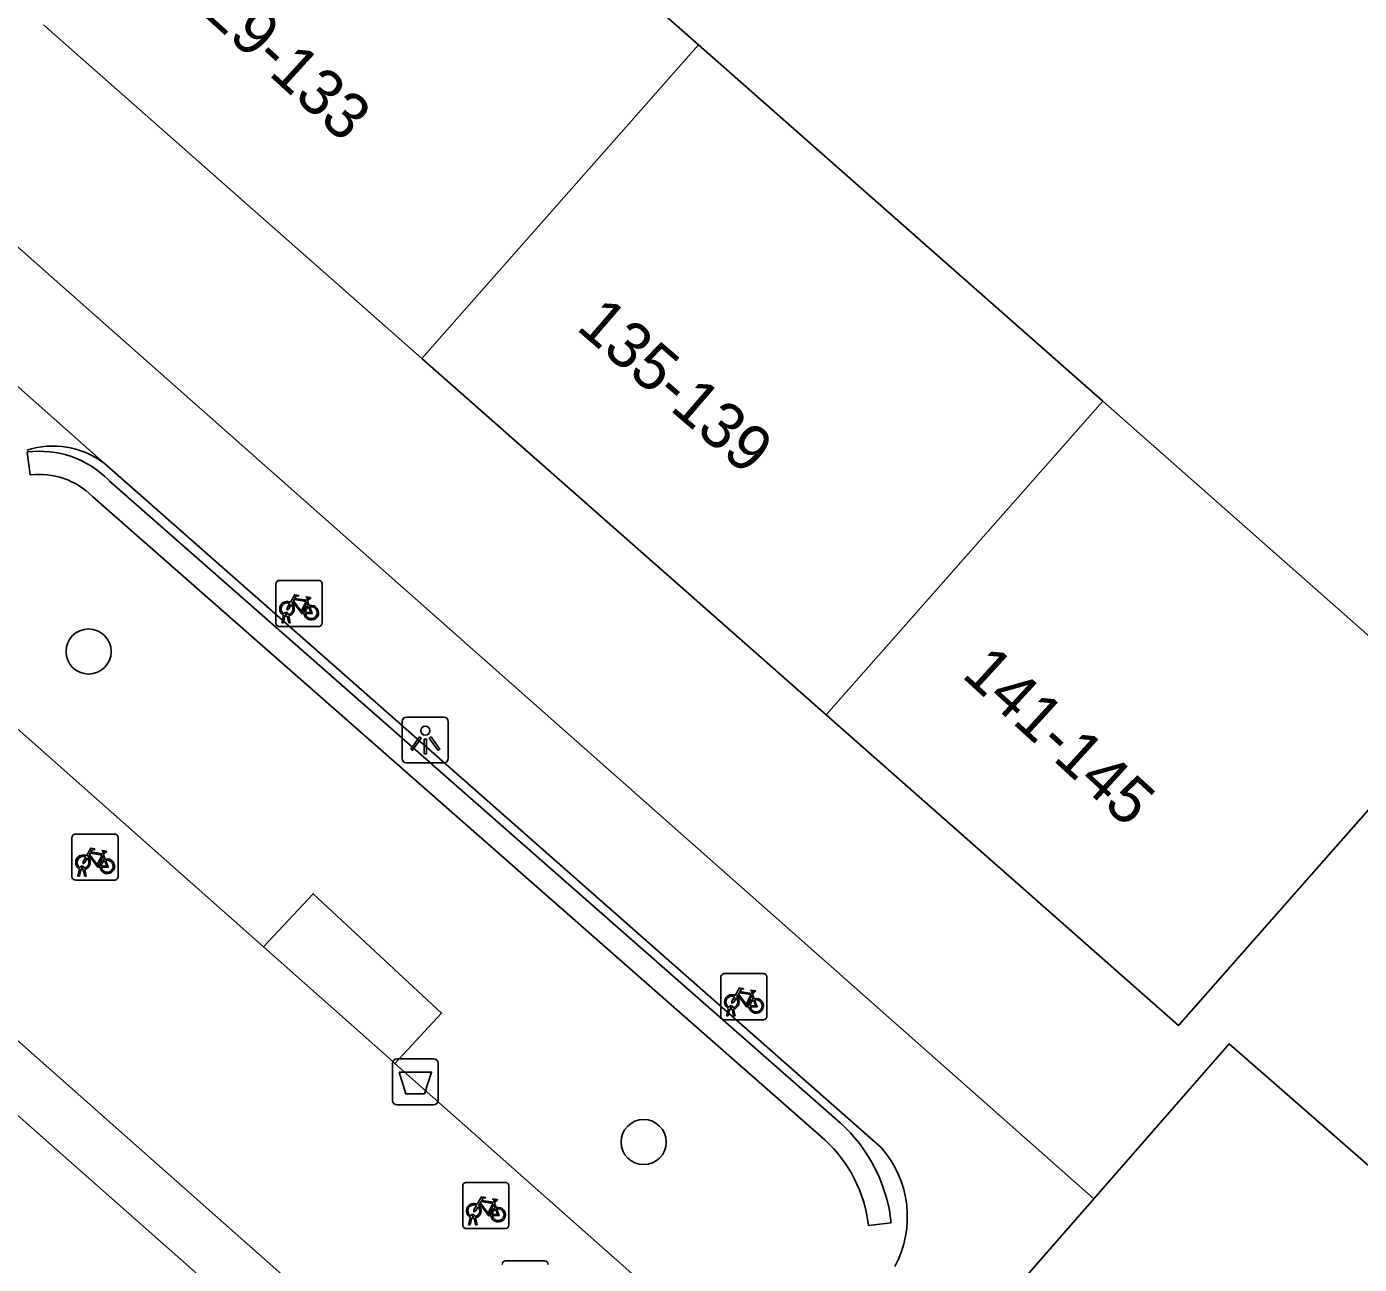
# Model space of a CAD drawing. Extents: x 162074 to 163034, y 381824 to 382557.
# Drawn here: x 162669.05 to 162697.93, y 382160.42 to 382187.25 of the extents above; entities that cross this region are included whole.
import ezdxf

# ---------------------------------------------------------------- set-up
doc = ezdxf.new("R2010")
doc.units = 0
for name, color, linetype in [('IMGEO_Afvalbak', 7, 'Continuous'), ('IMGEO_Boom', 7, 'Continuous'), ('IMGEO_Brandkraan', 7, 'Continuous'), ('IMGEO_Fietsenrek', 7, 'Continuous'), ('IMGEO_Fietspad_gesloten', 7, 'Continuous'), ('IMGEO_Haag', 7, 'Continuous'), ('IMGEO_Lichtpunt', 7, 'Continuous'), ('IMGEO_Pand', 7, 'Continuous'), ('IMGEO_Pand_nummerreeks', 7, 'Continuous'), ('IMGEO_Rijbaan_lokaal_open', 7, 'Continuous'), ('IMGEO_Voetpad_gesloten', 7, 'Continuous'), ('IMGEO_Voetpad_open', 7, 'Continuous')]:
    doc.layers.add(name, color=color, linetype=linetype)

msp = doc.modelspace()

# ---------------------------------------------------------------- linework, layer by layer
at = {"layer": 'IMGEO_Afvalbak'}
for p, q in [((162676.974, 382163.977), (162676.974, 382164.777)), ((162676.974, 382164.777), (162676.974, 382163.977)), ((162677.074, 382164.877), (162677.864, 382164.877)), ((162677.864, 382164.877), (162677.074, 382164.877)), ((162677.964, 382164.777), (162677.964, 382163.977)), ((162677.964, 382163.977), (162677.964, 382164.777)), ((162677.864, 382163.877), (162677.074, 382163.877)), ((162677.074, 382163.877), (162677.864, 382163.877))]:
    msp.add_line(p, q, dxfattribs=at)
msp.add_lwpolyline([(162677.117, 382164.591), (162677.821, 382164.591), (162677.672, 382164.121), (162677.266, 382164.121), (162677.117, 382164.591)], dxfattribs=at)
for centre, start, end in [((162677.074, 382164.777), 90, 180), ((162677.074, 382164.777), 90, 180), ((162677.864, 382164.777), 0, 90), ((162677.864, 382164.777), 360, 90), ((162677.074, 382163.977), 180, 270), ((162677.074, 382163.977), 180, 270), ((162677.864, 382163.977), 270, 0), ((162677.864, 382163.977), 270, 0)]:
    msp.add_arc(centre, 0.1, start, end, dxfattribs=at)
at = {"layer": 'IMGEO_Boom'}
for centre in [(162670.389, 382173.706), (162682.419, 382163.073)]:
    msp.add_circle(centre, 0.489, dxfattribs=at)
at = {"layer": 'IMGEO_Brandkraan'}
msp.add_line((162679.424, 382160.496), (162680.276, 382160.496), dxfattribs=at)
msp.add_lwpolyline([(162679.424, 382160.496), (162680.276, 382160.496)], dxfattribs=at)
for centre, start, end in [((162679.426, 382160.42), 91.552, 178.448), ((162679.426, 382160.42), 91.552, 178.448), ((162680.274, 382160.42), 1.552, 88.448), ((162680.274, 382160.42), 1.552, 88.448)]:
    msp.add_arc(centre, 0.0765, start, end, dxfattribs=at)
at = {"layer": 'IMGEO_Fietsenrek'}
for p, q in [((162674.449, 382174.322), (162674.449, 382175.163)), ((162674.449, 382175.163), (162674.449, 382174.322)), ((162674.524, 382175.247), (162675.365, 382175.247)), ((162675.365, 382175.247), (162674.524, 382175.247)), ((162675.449, 382175.172), (162675.449, 382174.331)), ((162675.449, 382174.331), (162675.449, 382175.172)), ((162675.136, 382174.796), (162675.172, 382174.701)), ((162674.576, 382174.331), (162674.615, 382174.491)), ((162674.645, 382174.479), (162674.61, 382174.331)), ((162674.687, 382174.503), (162674.686, 382174.507)), ((162674.728, 382174.331), (162674.694, 382174.473)), ((162674.718, 382174.514), (162674.719, 382174.507)), ((162674.726, 382174.477), (162674.761, 382174.331)), ((162675.374, 382174.247), (162674.533, 382174.247)), ((162674.533, 382174.247), (162675.374, 382174.247)), ((162674.61, 382174.331), (162674.576, 382174.331)), ((162674.761, 382174.331), (162674.728, 382174.331)), ((162670.028, 382168.825), (162670.028, 382169.666)), ((162670.028, 382169.666), (162670.028, 382168.825)), ((162670.103, 382169.75), (162670.944, 382169.75)), ((162670.944, 382169.75), (162670.103, 382169.75)), ((162671.028, 382169.675), (162671.028, 382168.834)), ((162671.028, 382168.834), (162671.028, 382169.675)), ((162670.715, 382169.299), (162670.751, 382169.204)), ((162670.155, 382168.834), (162670.194, 382168.994)), ((162670.224, 382168.982), (162670.189, 382168.834)), ((162670.266, 382169.006), (162670.265, 382169.01)), ((162670.307, 382168.834), (162670.273, 382168.976)), ((162670.297, 382169.017), (162670.298, 382169.01)), ((162670.305, 382168.98), (162670.34, 382168.834)), ((162670.953, 382168.75), (162670.112, 382168.75)), ((162670.112, 382168.75), (162670.953, 382168.75)), ((162670.189, 382168.834), (162670.155, 382168.834)), ((162670.34, 382168.834), (162670.307, 382168.834)), ((162684.09, 382165.799), (162684.09, 382166.64)), ((162684.09, 382166.64), (162684.09, 382165.799)), ((162684.165, 382166.724), (162685.006, 382166.724)), ((162685.006, 382166.724), (162684.165, 382166.724)), ((162685.09, 382166.649), (162685.09, 382165.808)), ((162685.09, 382165.808), (162685.09, 382166.649)), ((162684.777, 382166.273), (162684.813, 382166.178)), ((162684.217, 382165.808), (162684.256, 382165.968)), ((162684.251, 382165.808), (162684.217, 382165.808)), ((162684.286, 382165.956), (162684.251, 382165.808)), ((162684.328, 382165.98), (162684.327, 382165.984)), ((162684.369, 382165.808), (162684.335, 382165.95)), ((162684.359, 382165.991), (162684.36, 382165.984)), ((162684.367, 382165.954), (162684.402, 382165.808)), ((162684.402, 382165.808), (162684.369, 382165.808)), ((162685.015, 382165.724), (162684.174, 382165.724)), ((162684.174, 382165.724), (162685.015, 382165.724)), ((162678.497, 382161.273), (162678.497, 382162.114)), ((162678.497, 382162.114), (162678.497, 382161.273)), ((162678.572, 382162.198), (162679.413, 382162.198)), ((162679.413, 382162.198), (162678.572, 382162.198)), ((162679.497, 382162.123), (162679.497, 382161.282)), ((162679.497, 382161.282), (162679.497, 382162.123)), ((162679.184, 382161.747), (162679.22, 382161.652)), ((162678.624, 382161.282), (162678.663, 382161.442)), ((162678.693, 382161.43), (162678.658, 382161.282)), ((162678.735, 382161.454), (162678.734, 382161.458)), ((162678.766, 382161.465), (162678.767, 382161.458)), ((162678.774, 382161.428), (162678.809, 382161.282)), ((162679.422, 382161.198), (162678.581, 382161.198)), ((162678.581, 382161.198), (162679.422, 382161.198)), ((162678.658, 382161.282), (162678.624, 382161.282)), ((162678.776, 382161.282), (162678.742, 382161.424)), ((162678.809, 382161.282), (162678.776, 382161.282))]:
    msp.add_line(p, q, dxfattribs=at)
for points in [[(162674.783, 382174.721), (162674.731, 382174.631), (162674.691, 382174.606), (162674.692, 382174.653), (162674.747, 382174.747)], [(162674.762, 382174.773), (162674.857, 382174.937), (162674.943, 382174.923), (162674.945, 382174.914), (162674.889, 382174.903), (162674.862, 382174.858), (162675.118, 382174.817)], [(162675.058, 382174.529), (162675.008, 382174.529), (162674.817, 382174.78), (162674.798, 382174.748)], [(162675.105, 382174.792), (162674.848, 382174.833), (162674.831, 382174.804), (162674.998, 382174.584), (162675.105, 382174.792)], [(162675.153, 382174.694), (162675.123, 382174.771), (162675.014, 382174.553), (162675.057, 382174.553)], [(162675.118, 382174.817), (162675.143, 382174.866), (162675.137, 382174.87), (162675.114, 382174.874), (162675.102, 382174.881), (162675.101, 382174.884), (162675.103, 382174.889), (162675.198, 382174.874), (162675.2, 382174.864), (162675.19, 382174.851), (162675.178, 382174.845), (162675.164, 382174.851), (162675.136, 382174.796)], [(162675.087, 382174.553), (162675.207, 382174.552), (162675.163, 382174.666)], [(162675.183, 382174.673), (162675.238, 382174.528), (162675.088, 382174.528)], [(162670.362, 382169.224), (162670.31, 382169.134), (162670.27, 382169.109), (162670.271, 382169.156), (162670.326, 382169.25)], [(162670.341, 382169.276), (162670.436, 382169.44), (162670.522, 382169.426), (162670.524, 382169.417), (162670.468, 382169.406), (162670.441, 382169.361), (162670.697, 382169.32)], [(162670.637, 382169.032), (162670.587, 382169.032), (162670.396, 382169.283), (162670.377, 382169.251)], [(162670.684, 382169.295), (162670.427, 382169.336), (162670.41, 382169.307), (162670.577, 382169.087), (162670.684, 382169.295)], [(162670.732, 382169.197), (162670.702, 382169.274), (162670.593, 382169.056), (162670.636, 382169.056)], [(162670.697, 382169.32), (162670.722, 382169.369), (162670.716, 382169.373), (162670.693, 382169.377), (162670.681, 382169.384), (162670.68, 382169.387), (162670.682, 382169.392), (162670.777, 382169.377), (162670.779, 382169.367), (162670.769, 382169.354), (162670.757, 382169.348), (162670.743, 382169.354), (162670.715, 382169.299)], [(162670.666, 382169.056), (162670.786, 382169.055), (162670.742, 382169.169)], [(162670.762, 382169.176), (162670.817, 382169.031), (162670.667, 382169.031)], [(162684.403, 382166.25), (162684.498, 382166.414), (162684.584, 382166.4), (162684.586, 382166.391), (162684.53, 382166.38), (162684.503, 382166.335), (162684.759, 382166.294)], [(162684.759, 382166.294), (162684.784, 382166.343), (162684.778, 382166.347), (162684.755, 382166.351), (162684.743, 382166.358), (162684.742, 382166.361), (162684.744, 382166.366), (162684.839, 382166.351), (162684.841, 382166.341), (162684.831, 382166.328), (162684.819, 382166.322), (162684.805, 382166.328), (162684.777, 382166.273)], [(162684.424, 382166.198), (162684.372, 382166.108), (162684.332, 382166.083), (162684.333, 382166.13), (162684.388, 382166.224)], [(162684.699, 382166.006), (162684.649, 382166.006), (162684.458, 382166.257), (162684.439, 382166.225)], [(162684.746, 382166.269), (162684.489, 382166.31), (162684.472, 382166.281), (162684.639, 382166.061), (162684.746, 382166.269)], [(162684.794, 382166.171), (162684.764, 382166.248), (162684.655, 382166.03), (162684.698, 382166.03)], [(162684.728, 382166.03), (162684.848, 382166.029), (162684.804, 382166.143)], [(162684.824, 382166.15), (162684.879, 382166.005), (162684.729, 382166.005)], [(162678.81, 382161.724), (162678.905, 382161.888), (162678.991, 382161.874), (162678.993, 382161.865), (162678.937, 382161.854), (162678.91, 382161.809), (162679.166, 382161.768)], [(162679.106, 382161.48), (162679.056, 382161.48), (162678.865, 382161.731), (162678.846, 382161.699)], [(162679.153, 382161.743), (162678.896, 382161.784), (162678.879, 382161.755), (162679.046, 382161.535), (162679.153, 382161.743)], [(162679.201, 382161.645), (162679.171, 382161.722), (162679.062, 382161.504), (162679.105, 382161.504)], [(162679.166, 382161.768), (162679.191, 382161.817), (162679.185, 382161.821), (162679.162, 382161.825), (162679.15, 382161.832), (162679.149, 382161.835), (162679.151, 382161.84), (162679.246, 382161.825), (162679.248, 382161.815), (162679.238, 382161.802), (162679.226, 382161.796), (162679.212, 382161.802), (162679.184, 382161.747)], [(162678.831, 382161.672), (162678.779, 382161.582), (162678.739, 382161.557), (162678.74, 382161.604), (162678.795, 382161.698)], [(162679.135, 382161.504), (162679.255, 382161.503), (162679.211, 382161.617)], [(162679.231, 382161.624), (162679.286, 382161.479), (162679.136, 382161.479)]]:
    msp.add_lwpolyline(points, dxfattribs=at)
for centre, radius, start, end in [((162674.527, 382175.169), 0.0779, 92.4484, 184.2845), ((162674.527, 382175.169), 0.0779, 92.4484, 184.2845), ((162675.371, 382175.169), 0.0779, 2.4484, 94.2845), ((162675.371, 382175.169), 0.0779, 2.4484, 94.2845), ((162674.689, 382174.632), 0.159, 62.6766, 242.1369), ((162674.689, 382174.632), 0.129, 63.3192, 238.903), ((162674.689, 382174.632), 0.129, 283.6043, 43.4302), ((162674.689, 382174.632), 0.159, 283.5766, 46.6042), ((162674.669, 382174.503), 0.0499, 12.8025, 158.6934), ((162674.689, 382174.632), 0.159, 253.9967, 271.7867), ((162674.669, 382174.503), 0.0174, 12.8025, 163.4502), ((162674.689, 382174.632), 0.129, 253.415, 269.0204), ((162675.216, 382174.548), 0.159, 113.3408, 178.3217), ((162675.216, 382174.548), 0.159, 187.0065, 105.7708), ((162675.216, 382174.548), 0.129, 113.923, 177.9556), ((162675.216, 382174.548), 0.129, 188.6715, 104.5883), ((162674.527, 382174.325), 0.0779, 182.4484, 274.2845), ((162674.527, 382174.325), 0.0779, 182.4484, 274.2845), ((162675.371, 382174.325), 0.0779, 272.4484, 4.2845), ((162675.371, 382174.325), 0.0779, 272.4484, 4.2845), ((162670.106, 382169.672), 0.0779, 92.4484, 184.2845), ((162670.106, 382169.672), 0.0779, 92.4484, 184.2845), ((162670.95, 382169.672), 0.0779, 2.4484, 94.2845), ((162670.95, 382169.672), 0.0779, 2.4484, 94.2845), ((162670.268, 382169.135), 0.159, 62.6766, 242.1369), ((162670.268, 382169.135), 0.129, 63.3192, 238.903), ((162670.268, 382169.135), 0.129, 283.6043, 43.4302), ((162670.268, 382169.135), 0.159, 283.5766, 46.6042), ((162670.248, 382169.006), 0.0499, 12.8025, 158.6934), ((162670.268, 382169.135), 0.159, 253.9967, 271.7867), ((162670.248, 382169.006), 0.0174, 12.8025, 163.4502), ((162670.268, 382169.135), 0.129, 253.415, 269.0204), ((162670.795, 382169.051), 0.159, 113.3408, 178.3217), ((162670.795, 382169.051), 0.159, 187.0065, 105.7708), ((162670.795, 382169.051), 0.129, 113.923, 177.9556), ((162670.795, 382169.051), 0.129, 188.6715, 104.5883), ((162670.106, 382168.828), 0.0779, 182.4484, 274.2845), ((162670.106, 382168.828), 0.0779, 182.4484, 274.2845), ((162670.95, 382168.828), 0.0779, 272.4484, 4.2845), ((162670.95, 382168.828), 0.0779, 272.4484, 4.2845), ((162684.168, 382166.646), 0.0779, 92.4484, 184.2845), ((162684.168, 382166.646), 0.0779, 92.4484, 184.2845), ((162685.012, 382166.646), 0.0779, 2.4484, 94.2845), ((162685.012, 382166.646), 0.0779, 2.4484, 94.2845), ((162684.33, 382166.109), 0.159, 62.6766, 242.1369), ((162684.33, 382166.109), 0.129, 63.3192, 238.903), ((162684.33, 382166.109), 0.129, 283.6043, 43.4302), ((162684.33, 382166.109), 0.159, 283.5766, 46.6042), ((162684.857, 382166.025), 0.159, 113.3408, 178.3217), ((162684.857, 382166.025), 0.159, 187.0065, 105.7708), ((162684.857, 382166.025), 0.129, 113.923, 177.9556), ((162684.857, 382166.025), 0.129, 188.6715, 104.5883), ((162684.168, 382165.802), 0.0779, 182.4484, 274.2845), ((162684.168, 382165.802), 0.0779, 182.4484, 274.2845), ((162684.31, 382165.98), 0.0499, 12.8025, 158.6934), ((162684.33, 382166.109), 0.159, 253.9967, 271.7867), ((162684.31, 382165.98), 0.0174, 12.8025, 163.4502), ((162684.33, 382166.109), 0.129, 253.415, 269.0204), ((162685.012, 382165.802), 0.0779, 272.4484, 4.2845), ((162685.012, 382165.802), 0.0779, 272.4484, 4.2845), ((162678.575, 382162.12), 0.0779, 92.4484, 184.2845), ((162678.575, 382162.12), 0.0779, 92.4484, 184.2845), ((162679.419, 382162.12), 0.0779, 2.4484, 94.2845), ((162679.419, 382162.12), 0.0779, 2.4484, 94.2845), ((162678.737, 382161.583), 0.159, 62.6766, 242.1369), ((162678.737, 382161.583), 0.129, 63.3192, 238.903), ((162678.717, 382161.454), 0.0499, 12.8025, 158.6934), ((162678.737, 382161.583), 0.159, 253.9967, 271.7867), ((162678.717, 382161.454), 0.0174, 12.8025, 163.4502), ((162678.737, 382161.583), 0.129, 253.415, 269.0204), ((162678.737, 382161.583), 0.129, 283.6043, 43.4302), ((162678.737, 382161.583), 0.159, 283.5766, 46.6042), ((162679.264, 382161.499), 0.159, 113.3408, 178.3217), ((162679.264, 382161.499), 0.159, 187.0065, 105.7708), ((162679.264, 382161.499), 0.129, 113.923, 177.9556), ((162679.264, 382161.499), 0.129, 188.6715, 104.5883), ((162678.575, 382161.276), 0.0779, 182.4484, 274.2845), ((162678.575, 382161.276), 0.0779, 182.4484, 274.2845), ((162679.419, 382161.276), 0.0779, 272.4484, 4.2845), ((162679.419, 382161.276), 0.0779, 272.4484, 4.2845)]:
    msp.add_arc(centre, radius, start, end, dxfattribs=at)
at = {"layer": 'IMGEO_Fietspad_gesloten'}
msp.add_lwpolyline([(162681.455, 382154.112), (162663.777, 382169.764)], dxfattribs=at)
at = {"layer": 'IMGEO_Haag'}
for points in [[(162669.122, 382177.534), (162669.06, 382178.03)], [(162670.83, 382177.416), (162686.679, 382163.492)], [(162686.342, 382163.122), (162670.473, 382177.065)], [(162687.785, 382161.32), (162687.288, 382161.265)]]:
    msp.add_lwpolyline(points, dxfattribs=at)
for centre, radius, start, end in [((162669.322, 382175.927), 2.12, 44.6415, 97.0959), ((162669.322, 382175.929), 1.617, 44.615, 97.096), ((162684.354, 382160.94), 3.452, 6.3129, 47.6583), ((162684.351, 382160.939), 2.955, 6.3443, 47.6465)]:
    msp.add_arc(centre, radius, start, end, dxfattribs=at)
at = {"layer": 'IMGEO_Lichtpunt'}
for p, q in [((162677.187, 382172.191), (162677.187, 382171.384)), ((162677.187, 382172.191), (162677.187, 382171.384)), ((162678.089, 382172.286), (162677.281, 382172.286)), ((162678.089, 382172.286), (162677.281, 382172.286)), ((162678.183, 382171.384), (162678.183, 382172.191)), ((162678.183, 382171.384), (162678.183, 382172.191)), ((162677.281, 382171.29), (162678.089, 382171.29)), ((162677.281, 382171.29), (162678.089, 382171.29))]:
    msp.add_line(p, q, dxfattribs=at)
for points in [[(162677.561, 382171.855), (162677.6, 382171.827), (162677.412, 382171.565), (162677.374, 382171.592), (162677.561, 382171.855)], [(162677.773, 382171.827), (162677.811, 382171.854), (162677.998, 382171.592), (162677.959, 382171.564), (162677.773, 382171.827)], [(162677.663, 382171.807), (162677.71, 382171.807), (162677.71, 382171.485), (162677.663, 382171.485), (162677.663, 382171.807)]]:
    msp.add_lwpolyline(points, dxfattribs=at)
msp.add_circle((162677.686, 382171.989), 0.0994, dxfattribs=at)
for centre, start, end in [((162677.281, 382172.191), 90, 180), ((162677.281, 382172.191), 90, 180), ((162678.089, 382172.191), 0, 90), ((162678.089, 382172.191), 0, 90), ((162677.281, 382171.384), 180, 270), ((162677.281, 382171.384), 180, 270), ((162678.089, 382171.384), 270, 0), ((162678.089, 382171.384), 270, 360)]:
    msp.add_arc(centre, 0.0946, start, end, dxfattribs=at)
at = {"layer": 'IMGEO_Pand'}
for points in [[(162675.406, 382194.085), (162683.605, 382186.857)], [(162677.612, 382180.06), (162669.413, 382187.289)], [(162683.605, 382186.857), (162677.612, 382180.06)], [(162683.605, 382186.857), (162692.369, 382179.13)], [(162686.376, 382172.333), (162677.612, 382180.06)], [(162692.369, 382179.13), (162700.002, 382172.4), (162697.316, 382169.354), (162694.009, 382165.603), (162686.376, 382172.333)], [(162692.369, 382179.13), (162686.376, 382172.333)], [(162692.173, 382161.844), (162695.105, 382165.202), (162703.677, 382157.718)], [(162689.471, 382158.748), (162692.173, 382161.844)]]:
    msp.add_lwpolyline(points, dxfattribs=at)
at = {"layer": 'IMGEO_Rijbaan_lokaal_open'}
msp.add_lwpolyline([(162658.953, 382172.402), (162758.158, 382084.712)], dxfattribs=at)
at = {"layer": 'IMGEO_Voetpad_gesloten'}
for points in [[(162677.027, 382164.777), (162678.04, 382165.868), (162675.255, 382168.454), (162674.18, 382167.302)], [(162677.027, 382164.777), (162676.91, 382164.881), (162674.18, 382167.302)]]:
    msp.add_lwpolyline(points, dxfattribs=at)
at = {"layer": 'IMGEO_Voetpad_open'}
for points in [[(162633.334, 382213.898), (162692.173, 382161.844)], [(162670.725, 382177.786), (162667.197, 382180.919)], [(162670.725, 382177.786), (162687.572, 382162.947)], [(162674.18, 382167.302), (162667.189, 382173.499)], [(162683.872, 382158.709), (162677.027, 382164.777)]]:
    msp.add_lwpolyline(points, dxfattribs=at)
for centre, radius, start, end in [((162669.621, 382176.342), 1.818, 52.5993, 108.3875), ((162685.877, 382161.457), 2.257, 331.4702, 41.3277)]:
    msp.add_arc(centre, radius, start, end, dxfattribs=at)

# ---------------------------------------------------------------- texts
at = {"layer": 'IMGEO_Pand_nummerreeks'}
for s, rotation, p in [('129-133', 317.6264, (162672.292, 382188.022)), ('135-139', 319.3208, (162680.933, 382180.701)), ('141-145', 317.5638, (162689.288, 382173.173))]:
    msp.add_text(s, height=1, rotation=rotation, dxfattribs=at).set_placement(p)

doc.saveas('drawing.dxf')
